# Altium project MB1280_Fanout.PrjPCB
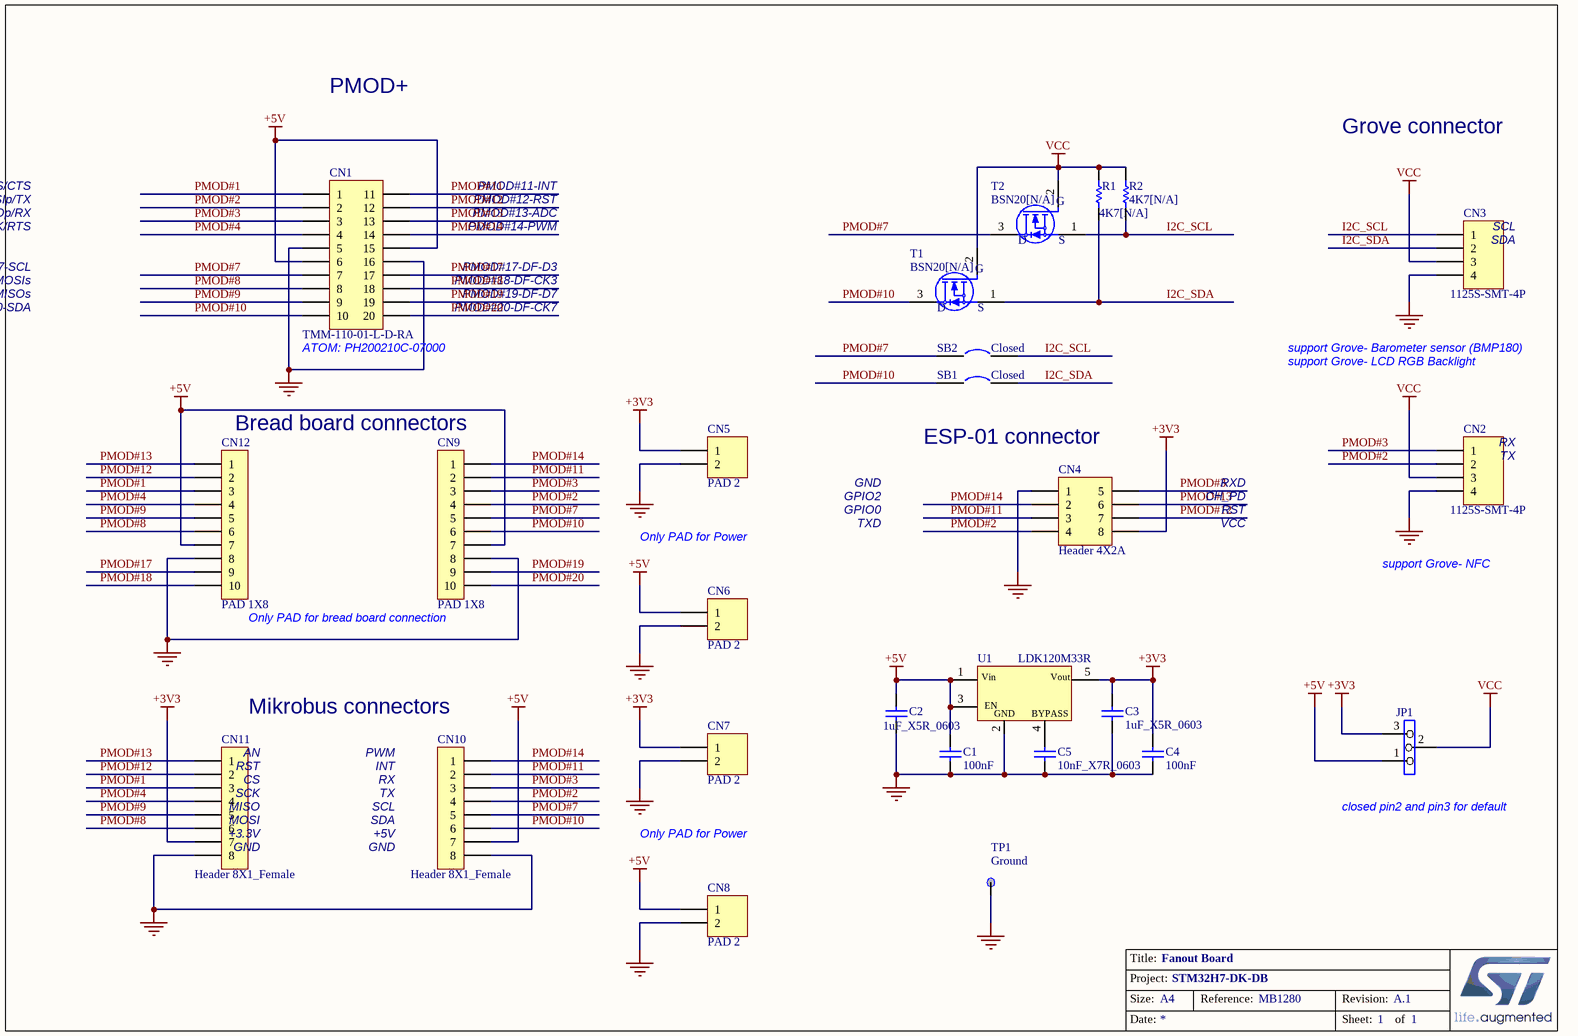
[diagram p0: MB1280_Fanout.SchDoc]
1 sheet, 26 parts. Net scope: global (net labels, ports and power ports of the same name join across sheets).
Board file: MB1280.PcbDoc

## Sheet MB1280_Fanout.SchDoc: Fanout Board
size A4; DocumentNumber: MB1280; Revision: A.1; SheetNumber: 1; SheetTotal: 1; Project: STM32H7-DK-DB

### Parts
C1  100nF  [0603C]
C2  1uF_X5R_0603  [0603C]
C3  1uF_X5R_0603  [0603C]
C4  100nF  [0603C]
C5  10nF_X7R_0603  [0603C]
CN1  TMM-110-01-L-D-RA  [2*10_MALE_2MM_H]
CN2  1125S-SMT-4P  [1X4_MALE_C]
CN3  1125S-SMT-4P  [1X4_MALE_C]
CN4  Header 4X2A  [HDR2X4_CEN1]
CN5  PAD 2  [HDR_2X1_2R54]
CN6  PAD 2  [HDR_2X1_2R54]
CN7  PAD 2  [HDR_2X1_2R54]
CN8  PAD 2  [HDR_2X1_2R54]
CN9  PAD 1X8  [1*10P_FEMALE]
CN10  Header 8X1_Female  [1*8P_FEMALE]
CN11  Header 8X1_Female  [1*8P_FEMALE]
CN12  PAD 1X8  [1*10P_FEMALE]
JP1  (no value)  [SIP3]
R1  4K7[N/A]  [0603R]
R2  4K7[N/A]  [0603R]
SB1  Closed  [SB_0603]
SB2  Closed  [SB_0603]
T1  BSN20[N/A]  [SOT23-213]
T2  BSN20[N/A]  [SOT23-213]
TP1  Ground  [TP_C4MM_PAD]
U1  LDK120M33R  [SOT-23-5L]

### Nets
+3V3: C3.1 C4.2 CN4.8 CN5.1 CN7.1 CN11.7 JP1.3 U1.5(Vout)
+5V: C1.2 C2.2 CN1.6 CN1.15 CN6.1 CN8.1 CN9.7 CN10.7 CN12.7 JP1.1 U1.1(Vin) U1.3(CE)
GND: C1.1 C2.1 C3.2 C4.1 C5.1 CN1.5 CN1.16 CN2.4 CN3.4 CN4.1 CN5.2 CN6.2 CN7.2 CN8.2 CN9.8 CN10.8 CN11.8 CN12.8 TP1.1 U1.2(GND)
VCC: CN2.3 CN3.3 JP1.2 R1.2 R2.2 T1.2(G) T2.2(G)
I2C_SCL: CN3.1 R2.1 SB2.2 T2.1(S)
I2C_SDA: CN3.2 R1.1 SB1.2 T1.1(S)
PMOD#1: CN1.1 CN11.3 CN12.3
PMOD#2: CN1.2 CN2.2 CN4.4 CN9.4 CN10.4
PMOD#3: CN1.3 CN2.1 CN4.5 CN9.3 CN10.3
PMOD#4: CN1.4 CN11.4 CN12.4
PMOD#7: CN1.7 CN9.5 CN10.5 SB2.1 T2.3(D)
PMOD#8: CN1.8 CN11.6 CN12.6
PMOD#9: CN1.9 CN11.5 CN12.5
PMOD#10: CN1.10 CN9.6 CN10.6 SB1.1 T1.3(D)
PMOD#11: CN1.11 CN4.3 CN9.2 CN10.2
PMOD#12: CN1.12 CN4.7 CN11.2 CN12.2
PMOD#13: CN1.13 CN4.6 CN11.1 CN12.1
PMOD#14: CN1.14 CN4.2 CN9.1 CN10.1
PMOD#17: CN1.17 CN12.9
PMOD#18: CN1.18 CN12.10
PMOD#19: CN1.19 CN9.9
PMOD#20: CN1.20 CN9.10
NetC5_2: C5.2 U1.4(BYPASS)

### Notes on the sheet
- PMOD+
- Grove connector
- PMOD#1-NSS/CTS
- PMOD#2-MOSIp/TX
- PMOD#3-MISOp/RX
- PMOD#4-SCK/RTS
- PMOD#11-INT
- PMOD#12-RST
- PMOD#13-ADC
- PMOD#14-PWM
- SCL
- SDA
- PMOD#7-SCL
- PMOD#8-MOSIs
- PMOD#9-MISOs
- PMOD#10-SDA
- PMOD#17-DF-D3
- PMOD#18-DF-CK3
- PMOD#19-DF-D7
- PMOD#20-DF-CK7
- (near CN1) ATOM: PH200210C-07000
- support Grove- Barometer sensor (BMP180)
- support Grove- LCD RGB Backlight
- Bread board connectors
- ESP-01 connector
- RX
- GND
- GPIO2
- GPIO0
- RXD
- CH_PD
- RST
- TX
- Only PAD for Power
- TXD
- VCC
- support Grove- NFC
- Only PAD for bread board connection
- Mikrobus connectors
- (near CN11) AN
- (near CN11) RST
- (near CN11) CS
- (near CN10) PWM
- (near CN10) INT
- (near CN11) SCK
- (near CN11) MISO
- (near CN11) MOSI
- (near CN11) +3.3V
- (near CN11) GND
- (near CN10) SCL
- (near CN10) SDA
- (near CN10) +5V
- (near CN10) GND
- (near JP1) closed pin2 and pin3 for default

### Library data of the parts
C1 C4 = Capacitor_ST: Capacitor 0402 / 0603 / 0805
C2 C3 = CAP SMD 0603  X5R 1µF 25V 10%: 0603  X5R 1µF; Rated voltage: 25V; Tolerance: 10%
C5 = CAP SMD 0603  X7R 10000PF 50V 10%: 0603  X7R 10NF; Order code RS: 2040779; Rated voltage: 50V; Tolerance: 10%
CN1 = Header 10X2A: Header, 10-Pin, Dual row
CN2 CN3 = Header 4
CN4 = Header 4X2A: Header, 4-Pin, Dual row
CN5-CN8 = Header 2: Header, 2-Pin
CN9 CN12 = Header 10X1_Female: Header, 10-Pin, Single row,female; Ordered by: Subcon; ECCN_US/EU: NA
CN10 CN11 = Header 8X1_Female: Header, 8-Pin, Single row,female; Ordered by: Subcon; ECCN_US/EU: NA
JP1 = Jumper3
R1 R2 = res1: Resistor; Value: 1K
SB1 SB2 = Circuit Breaker: Ordered by: Subcon; Comments: Solder bridge; ECCN_US/EU: NA
T1 T2 = 2N7000
TP1 = TP
U1 = LDK120M33R: 200 mA low quiescent current very low noise LDO; Manuf_1: STM; Provided: ST; Description: Ultra low drop-low noise BiCMOS voltage, regulators low ESR capacitors compatible; Ref St: 9176161; ECCN_US/EU: EAR99/NEC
